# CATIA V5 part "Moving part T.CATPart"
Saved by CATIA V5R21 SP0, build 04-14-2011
Part number: Part1
Material "Steel": density 7860 kg/m3, Young's modulus 2e+11 Pa, Poisson ratio 0.266, thermal expansion 1.17e-05 1/K
Bounding box of the stored display mesh (mm): x -120 to 120, y -2 to 36, z -14.5 to 320
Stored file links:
  C:\Users\MIRCEA\Desktop\PRRO\CATIAV5\Moving part T.CATPart
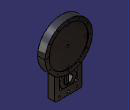
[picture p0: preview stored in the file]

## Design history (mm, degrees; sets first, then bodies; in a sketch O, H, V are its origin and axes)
Body1 (main body)
  Sketch1 on zx-plane, origin (0, 0, 0), H (-1, 0, 0), V (0, 0, 1)
    line L1 (70, -14.5) -> (-70, -14.5)
    circle A1 centre (0, 0) radius 6
    circle A2 centre (45, 0) radius 4.2
    circle A3 centre (-45, 0) radius 4.2
    point P5 (0, 200)
    circle A4 centre (0, 200) radius 100
    point P6 (-70, 20)
    line L2 (70, -14.5) -> (70, 102.5321)
    line L3 (-70, -14.5) -> (-70, 102.5321)
    arc A5 centre (0, 200) radius 120 from (70, 102.5321) to (-70, 102.5321) ccw
    point P9 (70, 102.5321)
    point P10 (0, 55)
    line L4 (45, 85) -> (45, 25)
    line L5 (45, 25) -> (-45, 25)
    line L6 (-45, 25) -> (-45, 85)
    line L7 (-45, 85) -> (45, 85)
    radius A1 = 6
    radius A2 = 4.2
    radius A3 = 4.2
    radius A4 = 100
    distance P5 O = 200
    distance O L1 = 14.5
    distance L5 L7 = 60
    horizontal: L1 H, L5 H, L7 H
    vertical: L2 V, L3 V, L4 V, L6 V
    coincidence: P9 L2
    equidistance: L4 L6 P10, L5 L7 P10
  Pad1: profile Sketch1, direction (0, 1, 0), length 34
  Plane1: type Offset, RefPlane zx-plane, Offset 2
  Sketch2 on Plane1, origin (0, 2, 0), H (-1, 0, 0), V (0, 0, 1)
    point P1 (0, 55)
    point P2 (46.188, 55)
    point P3 (23.094, 95)
    point P4 (-23.094, 95)
    point P5 (-46.188, 55)
    point P6 (-23.094, 15)
    point P7 (23.094, 15)
    point P8 (34.641, 75)
    line L1 (46.188, 55) -> (23.094, 95)
    line L2 (23.094, 95) -> (-23.094, 95)
    line L3 (-23.094, 95) -> (-46.188, 55)
    line L4 (-46.188, 55) -> (-23.094, 15)
    line L5 (-23.094, 15) -> (23.094, 15)
    line L6 (23.094, 15) -> (46.188, 55)
    construction line L7 (0, 55) -> (34.641, 75)
    construction circle A1 centre (0, 55) radius 46.188
    construction arc A2 centre (-23.094, 15) radius 46.188 from (-46.188, 55) to (23.094, 15) cw
    construction arc A3 centre (23.094, 95) radius 46.188 from (-23.094, 95) to (46.188, 55) ccw
    point P9 (0, 55)
    point P10 (25.9808, 55)
    point P11 (12.9904, 77.5)
    point P12 (-12.9904, 77.5)
    point P13 (-25.9808, 55)
    point P14 (-12.9904, 32.5)
    point P15 (12.9904, 32.5)
    point P16 (19.4856, 66.25)
    line L8 (25.9808, 55) -> (12.9904, 77.5)
    line L9 (12.9904, 77.5) -> (-12.9904, 77.5)
    line L10 (-12.9904, 77.5) -> (-25.9808, 55)
    line L11 (-25.9808, 55) -> (-12.9904, 32.5)
    line L12 (-12.9904, 32.5) -> (12.9904, 32.5)
    line L13 (12.9904, 32.5) -> (25.9808, 55)
    construction line L14 (0, 55) -> (19.4856, 66.25)
    construction circle A4 centre (0, 55) radius 25.9808
    construction arc A5 centre (-12.9904, 32.5) radius 25.9808 from (-25.9808, 55) to (12.9904, 32.5) cw
    construction arc A6 centre (12.9904, 77.5) radius 25.9808 from (-12.9904, 77.5) to (25.9808, 55) ccw
    point P17 (0, 200)
    point P18 (5, 197.1132)
    point P19 (5, 202.8868)
    point P20 (0, 205.7735)
    point P21 (-5, 202.8868)
    point P22 (-5, 197.1132)
    point P23 (0, 194.2265)
    point P24 (5, 200)
    line L15 (5, 197.1132) -> (5, 202.8868)
    line L16 (5, 202.8868) -> (0, 205.7735)
    line L17 (0, 205.7735) -> (-5, 202.8868)
    line L18 (-5, 202.8868) -> (-5, 197.1132)
    line L19 (-5, 197.1132) -> (0, 194.2265)
    line L20 (0, 194.2265) -> (5, 197.1132)
    construction line L21 (0, 200) -> (5, 200)
    construction circle A7 centre (0, 200) radius 5.7735
    construction arc A8 centre (-5, 197.1132) radius 5.7735 from (-5, 202.8868) to (0, 194.2265) cw
    construction arc A9 centre (5, 202.8868) radius 5.7735 from (0, 205.7735) to (5, 197.1132) ccw
    circle A10 centre (0, 200) radius 100
    distance L1 L4 = 80
    angle L7 H = 30
    distance L8 L11 = 45
    angle L14 H = 30
    distance L15 L18 = 10
    angle L21 H = 0
    radius A10 = 100
    coincidence: A1 P2, A1 P3, A1 P4, A1 P5, A1 P6, A1 P7, A2 P1, A3 P1, P9 A3, P9 A2, A4 P10, A4 P11, A4 P12, A4 P13, A4 P14, A4 P15, A5 P9, A6 P9, A7 P18, A7 P19, A7 P20, A7 P21, A7 P22, A7 P23, A8 P17, A9 P17
    midpoint: P8 L1, P16 L8, P24 L15
    parallelism: L1 L4, L8 L11, L15 L18
  Pad2: profile Sketch2, direction (0, 1, 0), length 30
  Plane2: type Offset, RefPlane Plane1, Offset 2
  Sketch3 on Plane2, origin (0, 4, 0), H (-1, 0, 0), V (0, 0, 1)
    line L1 (0, 0) -> (10, 0)
    line L2 (10, 0) -> (10, 86.7883)
    line L3 (0, 0) -> (-10, 0)
    line L4 (10, 86.7883) -> (-10, 86.7883)
    line L5 (-10, 86.7883) -> (-10, 0)
    length L1 = 10
    length L3 = 10
    horizontal: L1 H, L3 H, L4 H
    vertical: L2 V, L5 V
  Pad3: profile Sketch3, direction (0, 1, 0), length 26
  Sketch4 on zx-plane, origin (0, 0, 0), H (-1, 0, 0), V (0, 0, 1)
    circle A1 centre (0, 0) radius 6
    radius A1 = 6
  Pocket1: profile Sketch4, direction (0, 1, 0), through (limit type 6)
  Fillet1: radius 5, on edge [face of Pad1 from Sketch1.L3 | face of Pad1 from Sketch1.A5]; edge [face of Pad1 from Sketch1.A5 | face of Pad1 from Sketch1.L2]
  Chamfer1: length 5, angle 45, on edge [face of Pad1 from Sketch1.L7 | face of Pad1 from Sketch1.L6]; edge [face of Pad1 from Sketch1.L4 | face of Pad1 from Sketch1.L7]; edge [face of Pad1 from Sketch1.L5 | face of Pad1 from Sketch1.L4]; edge [face of Pad1 from Sketch1.L6 | face of Pad1 from Sketch1.L5]; edge [face of Pad1 from Sketch1.L2 | face of Pad1 from Sketch1.L1]; edge [face of Pad1 from Sketch1.L1 | face of Pad1 from Sketch1.L3]
  Chamfer2: length 5, angle 45, on edge [start face of Pad3 | face of Pad3 from Sketch3.L2]; edge [start face of Pad3 | face of Pad3 from Sketch3.L5]; edge [face of Pad3 from Sketch3.L5 | end face of Pad3]; edge [face of Pad3 from Sketch3.L2 | end face of Pad3]
  Plane3: type Offset, RefPlane zx-plane, Offset -2
  Sketch5 on Plane3, origin (0, -2, 0), H (-1, 0, 0), V (0, 0, 1)
    circle A1 centre (0, 200) radius 120
    circle A2 centre (0, 200) radius 100
    radius A1 = 120
    radius A2 = 100
  Pad4: profile Sketch5, direction (0, 1, 0), length 38
  Sketch6 on Plane3, origin (0, -2, 0), H (-1, 0, 0), V (0, 0, 1)
    point P1 (0, 310)
  Sketch7 on start face of Pad4, origin (0, -2, 310), H (1, 0, 0), V (0, 0, 1)
    point P1 (0, 0)
    reference projected point E1 (0, 0) from Sketch6.P1
    coincidence: E1 P1
  Hole1: placed by Sketch7, at (0, -2, 310) direction (0, 1, 0), diameter 5, through (limit type 6)
  CircPattern1: of Hole1, instances 12, angular step 30 {= 360.0*1 deg/CircPattern1.AngularNumber}, axis from start face of Pad4
  Sketch8 on Plane1, origin (0, 2, 0), H (-1, 0, 0), V (0, 0, 1)
    point P1 (0, 290)
    point P2 (0, 110)
    point P3 (90, 200)
    point P4 (-90, 200)
  Sketch9 on start face of Pad2, origin (0, 2, 110), H (1, 0, 0), V (0, 0, 1)
    point P1 (0, 0)
    reference projected point E1 (0, 0) from Sketch8.P2
    coincidence: E1 P1
  Hole2: placed by Sketch9, at (0, 2, 110) direction (0, 1, 0), diameter 10, through (limit type 6)
  Sketch10 on start face of Pad2, origin (90, 2, 200), H (1, 0, 0), V (0, 0, 1)
    point P1 (0, 0)
    reference projected point E1 (0, 0) from Sketch8.P4
    coincidence: E1 P1
  Hole3: placed by Sketch10, at (90, 2, 200) direction (0, 1, 0), diameter 10, through (limit type 6)
  Sketch11 on start face of Pad2, origin (0, 2, 290), H (1, 0, 0), V (0, 0, 1)
    point P1 (0, 0)
    reference projected point E1 (0, 0) from Sketch8.P1
    coincidence: E1 P1
  Hole4: placed by Sketch11, at (0, 2, 290) direction (0, 1, 0), diameter 10, through (limit type 6)
  Sketch12 on start face of Pad2, origin (-90, 2, 200), H (1, 0, 0), V (0, 0, 1)
    point P1 (0, 0)
    reference projected point E1 (0, 0) from Sketch8.P3
    coincidence: E1 P1
  Hole5: placed by Sketch12, at (-90, 2, 200) direction (0, 1, 0), diameter 10, through (limit type 6)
